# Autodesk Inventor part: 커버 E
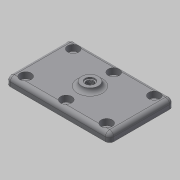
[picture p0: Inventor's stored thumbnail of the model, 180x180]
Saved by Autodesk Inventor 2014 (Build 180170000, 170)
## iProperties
Created: 2020-04
Part Number: 커버 E
Material: 알루미늄 6061
Document SubType Name: Modeling
Designer: mduedu
Density: 2.71 g/cm^3
Appearance: Default
Mass: 58.8274 g
Surface Area: 89.9592 cm^2
Volume: 21.7075 cm^3
Author: mduedu
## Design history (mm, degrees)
sketch "스케치1"
  geometry: L1 (37, 23)-(-37, 23); L2 (-37, 23)-(-37, -23); L3 (-37, -23)-(37, -23); L4 (37, -23)-(37, 23); L5 (37, 23)-(-37, -23); L6 (-37, 23)-(37, -23); 1 further point
  constraints: 12 end point, 2 midpoint, 2 parallel, 1 horizontal, 1 perpendicular
  dimensions: "d0" = 74 distance of L3.end L2.end; "d1" = 46 distance of L2.end L1.end
extrude "돌출1" new body sketch "스케치1" distance "d2" = 6; taper "d3" = 0 deg
sketch "스케치2"
  geometry: C1 r 6 at (0, 0); 1 further point
  constraints: 1 centre point, 1 coincident
  dimensions: "d4" = 12 diameter of C1
extrude "돌출2" join sketch "스케치2" distance "d5" = 3; taper "d6" = 0 deg
fillet "모깎기1" dims "d7" = 3
fillet "모깎기2" dims "d8" = 3
fillet "모깎기3" dims "d9" = 3
sketch "스케치3"
  geometry: L1 (-30, -13)-(30, -13); L2 (30, -13)-(30, 13); L3 (30, 13)-(-30, 13); L4 (-30, 13)-(-30, -13); L5 (-30, -13)-(30, 13); L6 (30, -13)-(-30, 13); 1 further point
  constraints: 12 end point, 2 midpoint, 2 parallel, 1 horizontal, 1 perpendicular
  dimensions: "d10" = 60 distance of L3.end L2.end; "d11" = 26 distance of L2.end L1.end
extrude "돌출3" join sketch "스케치3" distance "d12" = 2; taper "d13" = 0 deg
fillet "모깎기4" dims "d14" = 3
chamfer "모따기1" distance "d15" = 0.5; stored, may be unused: second distance "d16" = 2, angle "d17" = 45 deg
sketch "스케치4"
  geometry: L1 (-29, -17)-(29, -17); L2 (29, -17)-(29, 17); L3 (29, 17)-(-29, 17); L4 (-29, 17)-(-29, -17); L5 (-29, -17)-(29, 17); L6 (29, -17)-(-29, 17); 7 further points
  constraints: 12 end point, 4 coincident, 4 midpoint, 2 parallel, 1 horizontal, 1 perpendicular
  dimensions: "d18" = 58 distance of L3.end L2.end; "d19" = 34 distance of L2.end L1.end
hole "구멍1" sketch "스케치4" at (-29, 17), (-29, -17), (29, -17), (29, 17), (0, 17), (0, -17) diameter "d20" = 4.5; stored, may be unused: countersink angle "d24" = 90 deg, drill point angle "d26" = 118 deg; dims "d21" = 6, "d22" = 8, "d23" = 4.4, "d25" = 8
hole "구멍2" diameter "d29" = 5.188; stored, may be unused: countersink angle "d33" = 90 deg, drill point angle "d35" = 118 deg; dims "d27" = 10, "d28" = 10, "d30" = 6, "d31" = 8, "d32" = 4.4, "d34" = 8
sketch "스케치5"
  geometry: C1 r 3.5 at (0, 0); 1 further point
  constraints: 1 centre point, 1 coincident
  dimensions: "d36" = 7 diameter of C1
extrude "돌출4" cut sketch "스케치5" distance "d37" = 1; taper "d38" = 0 deg
node "솔리드1"
